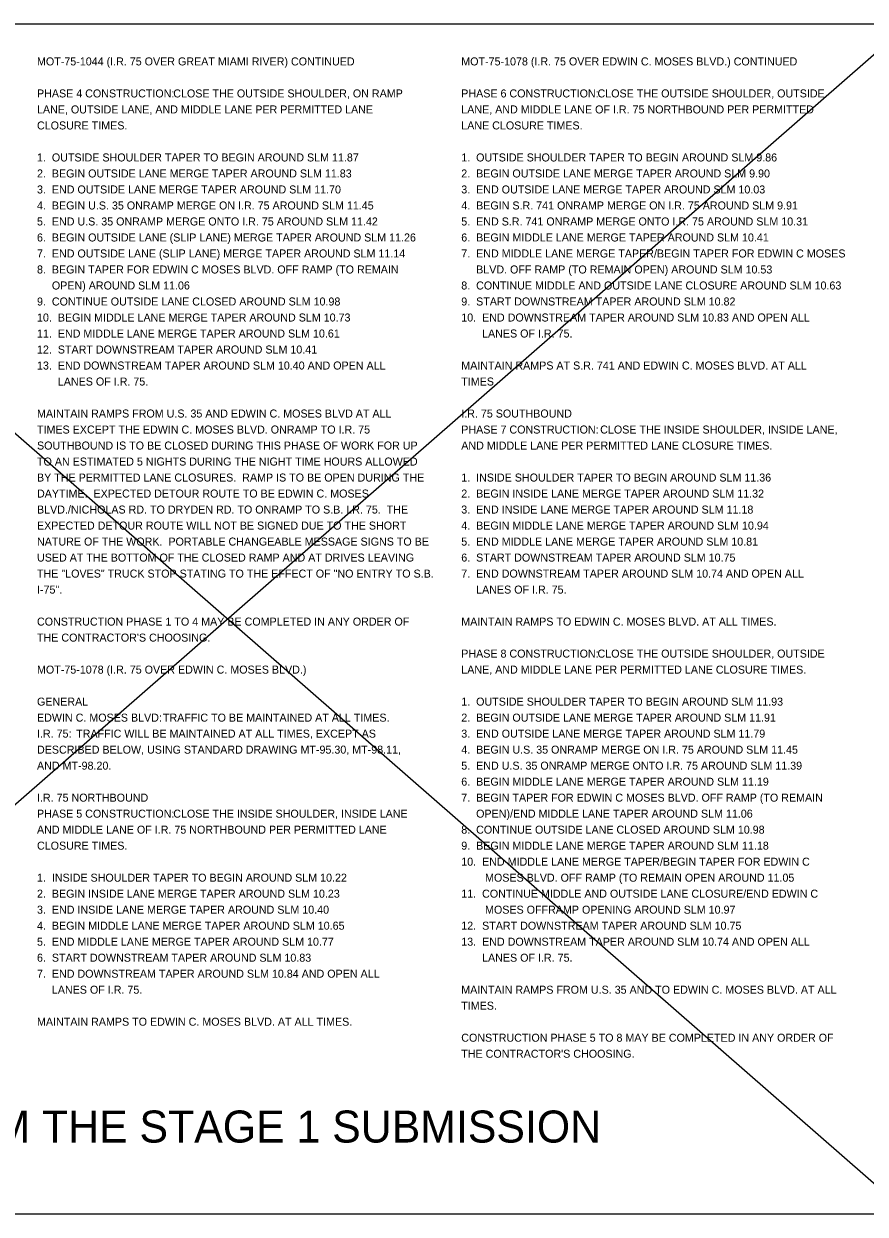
# Model space of a CAD drawing. Extents: x -25.5 to 52.6, y -2.3 to 22.
# Drawn here: x -17.16 to -2.45, y 0.89 to 21.72 of the extents above; entities that cross this region are included whole.
import ezdxf

# ---------------------------------------------------------------- set-up
doc = ezdxf.new("R2010")
doc.units = 0
doc.layers.add('Default', color=7, linetype='Continuous')
doc.layers.add('SH_Text', color=7, linetype='Continuous')

msp = doc.modelspace()

# ---------------------------------------------------------------- linework, layer by layer
at = {"layer": 'Default'}
msp.add_lwpolyline([(-25.517, 21.716), (-1.676, 21.716), (-1.676, 0.891), (-25.517, 0.891)], close=True, dxfattribs=at)
at = {"layer": 'SH_Text'}
for p, q in [((-25.517, 21.716), (-1.676, 0.891)), ((-1.676, 21.716), (-25.517, 0.891))]:
    msp.add_line(p, q, dxfattribs=at)

# ---------------------------------------------------------------- texts
for s, height, p in [('MOT-75-1044 (I.R. 75 OVER GREAT MIAMI RIVER) CONTINUED', 0.14, (-16.931, 20.988)), ('MOT-75-1078 (I.R. 75 OVER EDWIN C. MOSES BLVD.) CONTINUED', 0.14, (-9.511, 20.988)), ('PHASE 4 CONSTRUCTION:', 0.14, (-16.931, 20.428)), (' CLOSE THE OUTSIDE SHOULDER, ON RAMP ', 0.14, (-14.6, 20.428)), ('PHASE 6 CONSTRUCTION:', 0.14, (-9.511, 20.428)), (' CLOSE THE OUTSIDE SHOULDER, OUTSIDE ', 0.14, (-7.18, 20.428)), ('LANE, OUTSIDE LANE, AND MIDDLE LANE PER PERMITTED LANE ', 0.14, (-16.931, 20.148)), ('LANE, AND MIDDLE LANE OF I.R. 75 NORTHBOUND PER PERMITTED ', 0.14, (-9.511, 20.148)), ('CLOSURE TIMES.', 0.14, (-16.931, 19.868)), ('LANE CLOSURE TIMES.', 0.14, (-9.511, 19.868)), ('1.  OUTSIDE SHOULDER TAPER TO BEGIN AROUND SLM 11.87', 0.14, (-16.931, 19.308)), ('1.  OUTSIDE SHOULDER TAPER TO BEGIN AROUND SLM 9.86', 0.14, (-9.511, 19.308)), ('2.  BEGIN OUTSIDE LANE MERGE TAPER AROUND SLM 11.83', 0.14, (-16.931, 19.028)), ('2.  BEGIN OUTSIDE LANE MERGE TAPER AROUND SLM 9.90', 0.14, (-9.511, 19.028)), ('3.  END OUTSIDE LANE MERGE TAPER AROUND SLM 11.70', 0.14, (-16.931, 18.748)), ('3.  END OUTSIDE LANE MERGE TAPER AROUND SLM 10.03', 0.14, (-9.511, 18.748)), ('4.  BEGIN U.S. 35 ONRAMP MERGE ON I.R. 75 AROUND SLM 11.45', 0.14, (-16.931, 18.468)), ('4.  BEGIN S.R. 741 ONRAMP MERGE ON I.R. 75 AROUND SLM 9.91', 0.14, (-9.511, 18.468)), ('5.  END U.S. 35 ONRAMP MERGE ONTO I.R. 75 AROUND SLM 11.42', 0.14, (-16.931, 18.188)), ('5.  END S.R. 741 ONRAMP MERGE ONTO I.R. 75 AROUND SLM 10.31', 0.14, (-9.511, 18.188)), ('6.  BEGIN OUTSIDE LANE (SLIP LANE) MERGE TAPER AROUND SLM 11.26', 0.14, (-16.931, 17.908)), ('6.  BEGIN MIDDLE LANE MERGE TAPER AROUND SLM 10.41', 0.14, (-9.511, 17.908)), ('7.  END OUTSIDE LANE (SLIP LANE) MERGE TAPER AROUND SLM 11.14', 0.14, (-16.931, 17.628)), ('7.  END MIDDLE LANE MERGE TAPER/BEGIN TAPER FOR EDWIN C MOSES', 0.14, (-9.511, 17.628)), ('8.  BEGIN TAPER FOR EDWIN C MOSES BLVD. OFF RAMP (TO REMAIN', 0.14, (-16.931, 17.348)), ('     BLVD. OFF RAMP (TO REMAIN OPEN) AROUND SLM 10.53', 0.14, (-9.511, 17.348)), ('     OPEN) AROUND SLM 11.06', 0.14, (-16.931, 17.068)), ('8.  CONTINUE MIDDLE AND OUTSIDE LANE CLOSURE AROUND SLM 10.63', 0.14, (-9.511, 17.068)), ('9.  CONTINUE OUTSIDE LANE CLOSED AROUND SLM 10.98', 0.14, (-16.931, 16.788)), ('9.  START DOWNSTREAM TAPER AROUND SLM 10.82', 0.14, (-9.511, 16.788)), ('10.  BEGIN MIDDLE LANE MERGE TAPER AROUND SLM 10.73', 0.14, (-16.931, 16.508)), ('10.  END DOWNSTREAM TAPER AROUND SLM 10.83 AND OPEN ALL', 0.14, (-9.511, 16.508)), ('11.  END MIDDLE LANE MERGE TAPER AROUND SLM 10.61', 0.14, (-16.931, 16.228)), ('       LANES OF I.R. 75.', 0.14, (-9.511, 16.228)), ('12.  START DOWNSTREAM TAPER AROUND SLM 10.41', 0.14, (-16.931, 15.948)), ('13.  END DOWNSTREAM TAPER AROUND SLM 10.40 AND OPEN ALL', 0.14, (-16.931, 15.668)), ('MAINTAIN RAMPS AT S.R. 741 AND EDWIN C. MOSES BLVD. AT ALL ', 0.14, (-9.511, 15.668)), ('       LANES OF I.R. 75.', 0.14, (-16.931, 15.388)), ('TIMES.', 0.14, (-9.511, 15.388)), ('MAINTAIN RAMPS FROM U.S. 35 AND EDWIN C. MOSES BLVD AT ALL ', 0.14, (-16.931, 14.828)), ('I.R. 75 SOUTHBOUND', 0.14, (-9.511, 14.828)), ('TIMES EXCEPT THE EDWIN C. MOSES BLVD. ONRAMP TO I.R. 75 ', 0.14, (-16.931, 14.548)), ('PHASE 7 CONSTRUCTION:  ', 0.14, (-9.511, 14.548)), ('CLOSE THE INSIDE SHOULDER, INSIDE LANE, ', 0.14, (-7.081, 14.548)), ('SOUTHBOUND IS TO BE CLOSED DURING THIS PHASE OF WORK FOR UP ', 0.14, (-16.931, 14.268)), ('AND MIDDLE LANE PER PERMITTED LANE CLOSURE TIMES.', 0.14, (-9.511, 14.268)), ('TO AN ESTIMATED 5 NIGHTS DURING THE NIGHT TIME HOURS ALLOWED ', 0.14, (-16.931, 13.988)), ('BY THE PERMITTED LANE CLOSURES.  RAMP IS TO BE OPEN DURING THE ', 0.14, (-16.931, 13.708)), ('1.  INSIDE SHOULDER TAPER TO BEGIN AROUND SLM 11.36', 0.14, (-9.511, 13.708)), ('DAYTIME.  EXPECTED DETOUR ROUTE TO BE EDWIN C. MOSES ', 0.14, (-16.931, 13.428)), ('2.  BEGIN INSIDE LANE MERGE TAPER AROUND SLM 11.32', 0.14, (-9.511, 13.428)), ('BLVD./NICHOLAS RD. TO DRYDEN RD. TO ONRAMP TO S.B. I.R. 75.  THE ', 0.14, (-16.931, 13.148)), ('3.  END INSIDE LANE MERGE TAPER AROUND SLM 11.18', 0.14, (-9.511, 13.148)), ('EXPECTED DETOUR ROUTE WILL NOT BE SIGNED DUE TO THE SHORT ', 0.14, (-16.931, 12.868)), ('4.  BEGIN MIDDLE LANE MERGE TAPER AROUND SLM 10.94', 0.14, (-9.511, 12.868)), ('NATURE OF THE WORK.  PORTABLE CHANGEABLE MESSAGE SIGNS TO BE ', 0.14, (-16.931, 12.588)), ('5.  END MIDDLE LANE MERGE TAPER AROUND SLM 10.81', 0.14, (-9.511, 12.588)), ('USED AT THE BOTTOM OF THE CLOSED RAMP AND AT DRIVES LEAVING ', 0.14, (-16.931, 12.308)), ('6.  START DOWNSTREAM TAPER AROUND SLM 10.75', 0.14, (-9.511, 12.308)), ('THE "LOVES" TRUCK STOP STATING TO THE EFFECT OF "NO ENTRY TO S.B. ', 0.14, (-16.931, 12.028)), ('7.  END DOWNSTREAM TAPER AROUND SLM 10.74 AND OPEN ALL', 0.14, (-9.511, 12.028)), ('I-75". ', 0.14, (-16.931, 11.748)), ('     LANES OF I.R. 75.', 0.14, (-9.511, 11.748)), ('CONSTRUCTION PHASE 1 TO 4 MAY BE COMPLETED IN ANY ORDER OF ', 0.14, (-16.931, 11.188)), ('MAINTAIN RAMPS TO EDWIN C. MOSES BLVD. AT ALL TIMES.', 0.14, (-9.511, 11.188)), ("THE CONTRACTOR'S CHOOSING. ", 0.14, (-16.931, 10.908)), ('PHASE 8 CONSTRUCTION:', 0.14, (-9.511, 10.628)), (' CLOSE THE OUTSIDE SHOULDER, OUTSIDE ', 0.14, (-7.18, 10.628)), ('MOT-75-1078 (I.R. 75 OVER EDWIN C. MOSES BLVD.)', 0.14, (-16.931, 10.348)), ('LANE, AND MIDDLE LANE PER PERMITTED LANE CLOSURE TIMES.', 0.14, (-9.511, 10.348)), ('GENERAL', 0.14, (-16.931, 9.788)), ('1.  OUTSIDE SHOULDER TAPER TO BEGIN AROUND SLM 11.93', 0.14, (-9.511, 9.788)), ('EDWIN C. MOSES BLVD: ', 0.14, (-16.931, 9.508)), ('TRAFFIC TO BE MAINTAINED AT ALL TIMES.', 0.14, (-14.729, 9.508)), ('2.  BEGIN OUTSIDE LANE MERGE TAPER AROUND SLM 11.91', 0.14, (-9.511, 9.508)), ('I.R. 75: ', 0.14, (-16.931, 9.228)), ('TRAFFIC WILL BE MAINTAINED AT ALL TIMES, EXCEPT AS ', 0.14, (-16.246, 9.228)), ('3.  END OUTSIDE LANE MERGE TAPER AROUND SLM 11.79', 0.14, (-9.511, 9.228)), ('DESCRIBED BELOW, USING STANDARD DRAWING MT-95.30, MT-98.11, ', 0.14, (-16.931, 8.948)), ('4.  BEGIN U.S. 35 ONRAMP MERGE ON I.R. 75 AROUND SLM 11.45', 0.14, (-9.511, 8.948)), ('AND MT-98.20.', 0.14, (-16.931, 8.668)), ('5.  END U.S. 35 ONRAMP MERGE ONTO I.R. 75 AROUND SLM 11.39', 0.14, (-9.511, 8.668)), ('6.  BEGIN MIDDLE LANE MERGE TAPER AROUND SLM 11.19', 0.14, (-9.511, 8.388)), ('I.R. 75 NORTHBOUND', 0.14, (-16.931, 8.108)), ('7.  BEGIN TAPER FOR EDWIN C MOSES BLVD. OFF RAMP (TO REMAIN', 0.14, (-9.511, 8.108)), ('PHASE 5 CONSTRUCTION:', 0.14, (-16.931, 7.828)), (' CLOSE THE INSIDE SHOULDER, INSIDE LANE ', 0.14, (-14.6, 7.828)), ('     OPEN)/END MIDDLE LANE TAPER AROUND SLM 11.06', 0.14, (-9.511, 7.828)), ('AND MIDDLE LANE OF I.R. 75 NORTHBOUND PER PERMITTED LANE ', 0.14, (-16.931, 7.548)), ('8.  CONTINUE OUTSIDE LANE CLOSED AROUND SLM 10.98', 0.14, (-9.511, 7.548)), ('CLOSURE TIMES.', 0.14, (-16.931, 7.268)), ('9.  BEGIN MIDDLE LANE MERGE TAPER AROUND SLM 11.18', 0.14, (-9.511, 7.268)), ('10.  END MIDDLE LANE MERGE TAPER/BEGIN TAPER FOR EDWIN C', 0.14, (-9.511, 6.988)), ('1.  INSIDE SHOULDER TAPER TO BEGIN AROUND SLM 10.22', 0.14, (-16.931, 6.708)), ('        MOSES BLVD. OFF RAMP (TO REMAIN OPEN AROUND 11.05', 0.14, (-9.511, 6.708)), ('2.  BEGIN INSIDE LANE MERGE TAPER AROUND SLM 10.23', 0.14, (-16.931, 6.428)), ('11.  CONTINUE MIDDLE AND OUTSIDE LANE CLOSURE/END EDWIN C', 0.14, (-9.511, 6.428)), ('3.  END INSIDE LANE MERGE TAPER AROUND SLM 10.40', 0.14, (-16.931, 6.148)), ('        MOSES OFFRAMP OPENING AROUND SLM 10.97', 0.14, (-9.511, 6.148)), ('4.  BEGIN MIDDLE LANE MERGE TAPER AROUND SLM 10.65', 0.14, (-16.931, 5.868)), ('12.  START DOWNSTREAM TAPER AROUND SLM 10.75', 0.14, (-9.511, 5.868)), ('5.  END MIDDLE LANE MERGE TAPER AROUND SLM 10.77', 0.14, (-16.931, 5.588)), ('13.  END DOWNSTREAM TAPER AROUND SLM 10.74 AND OPEN ALL', 0.14, (-9.511, 5.588)), ('6.  START DOWNSTREAM TAPER AROUND SLM 10.83', 0.14, (-16.931, 5.308)), ('       LANES OF I.R. 75.', 0.14, (-9.511, 5.308)), ('7.  END DOWNSTREAM TAPER AROUND SLM 10.84 AND OPEN ALL', 0.14, (-16.931, 5.028)), ('     LANES OF I.R. 75.', 0.14, (-16.931, 4.748)), ('MAINTAIN RAMPS FROM U.S. 35 AND TO EDWIN C. MOSES BLVD. AT ALL ', 0.14, (-9.511, 4.748)), ('TIMES.', 0.14, (-9.511, 4.468)), ('MAINTAIN RAMPS TO EDWIN C. MOSES BLVD. AT ALL TIMES.', 0.14, (-16.931, 4.188)), ('CONSTRUCTION PHASE 5 TO 8 MAY BE COMPLETED IN ANY ORDER OF ', 0.14, (-9.511, 3.908)), ("THE CONTRACTOR'S CHOOSING.", 0.14, (-9.511, 3.628)), ('NOTES FROM THE STAGE 1 SUBMISSION', 0.56, (-22.045, 2.144))]:
    msp.add_text(s, height=height, dxfattribs=at).set_placement(p)

doc.saveas('drawing.dxf')
